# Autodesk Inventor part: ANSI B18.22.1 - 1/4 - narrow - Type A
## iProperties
Comments: To add or edit properties for Autodesk Inventor files, use iProperties.
Created: 2005-06
Part Number: ANSI B18.22.1 - 1/4 - narrow - Type A
Vendor: Autodesk Inc.
Document SubType Name: Modeling
Designer: John Blackburn
Material: Default
Description: Washer A
Standard: ANSI B18.22.1
Alert: To add or edit properties for Autodesk Inventor files, use iProperties.
Control State: 0
Master: False
Checked Out: False
Shininess: 64.0
Length Units: 11272
Angle Units: 11279
Time Units: 11290
Mass Units: 11286
Length Display Precision: 3
Angle Display Precision: 2
Compacted: True
Classification: un/spsc 31161807
Density: 0.0
Volumn: 0.0
Area: 0.0
PropertySet Name: Model Information
Author: John Blackburn
Revision Number: 8
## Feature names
1. Body [Extrusion]
